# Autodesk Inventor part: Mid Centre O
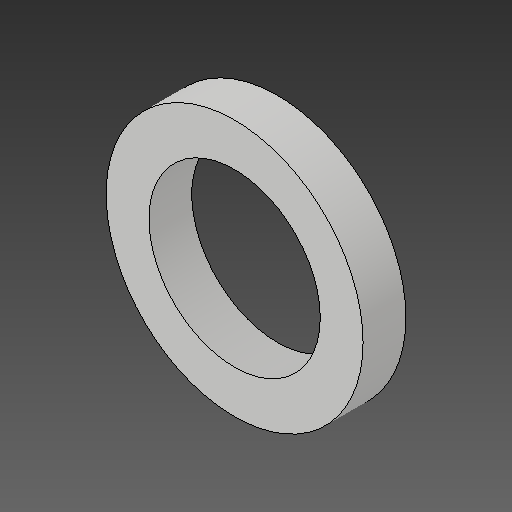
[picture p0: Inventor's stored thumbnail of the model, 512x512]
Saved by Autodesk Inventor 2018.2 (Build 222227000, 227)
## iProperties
Created: 2018-03
Part Number: Mid Centre O
Material: Generic
Document SubType Name: Modeling
Designer: PeterMaxwell-Stewart
Mass: 1.9635 g
Surface Area: 15.708 cm^2
Volume: 1.9635 cm^3
Density: 1 g/cm^3
Appearance: Default
Author: PeterMaxwell-Stewart
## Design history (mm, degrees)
derived "O's and X's.ipt"
feature "Mid Centre O::O's and X's.ipt" dims "d0" = 10
tag "TaggingFeature1"
body "Solid1"
